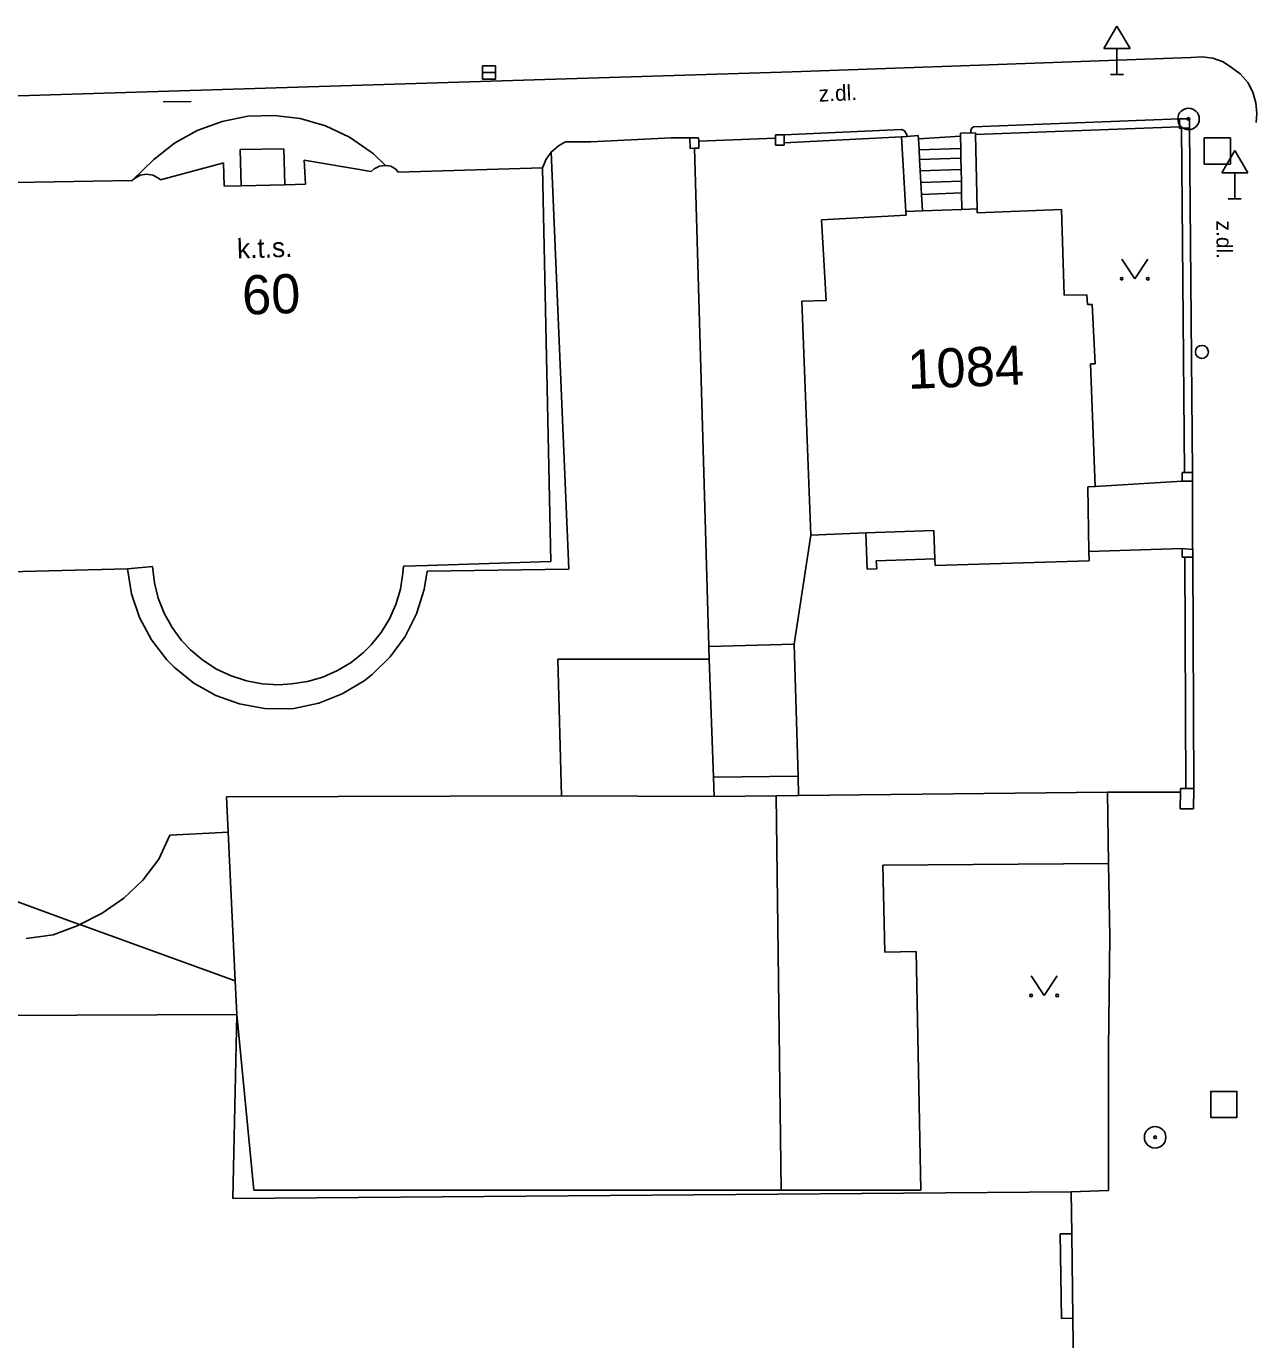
# Model space of a CAD drawing. Extents: x -642282 to -641982, y -1041678 to -1041427.
# Drawn here: x -642054.4 to -642007.5, y -1041554.9 to -1041504.6 of the extents above; entities that cross this region are included whole.
import ezdxf

# ---------------------------------------------------------------- set-up
doc = ezdxf.new("R2010")
doc.units = 0
for name, color, linetype in [('Budovy', 7, 'Continuous'), ('Ploty', 7, 'Continuous'), ('Pol_bod_pole', 7, 'Continuous'), ('Popis objektů', 7, 'Continuous'), ('Popis povrchů', 7, 'Continuous'), ('Popis ČP_ ČE', 7, 'Continuous'), ('Pris-HUP', 7, 'Continuous'), ('Rozhraní ploch 1', 7, 'Continuous'), ('Rozhraní ploch 2', 7, 'Continuous'), ('Svodidla_zábr_', 7, 'Continuous'), ('Vstup na pozemky', 7, 'Continuous'), ('Znaky kanalizace', 7, 'Continuous'), ('Znaky plyn', 7, 'Continuous'), ('Značky doprava', 7, 'Continuous'), ('Značky KM', 7, 'Continuous'), ('Šachty ner_', 7, 'Continuous')]:
    doc.layers.add(name, color=color, linetype=linetype)

msp = doc.modelspace()

# ---------------------------------------------------------------- linework, layer by layer
at = {"layer": 'Budovy'}
for p, q in [((-642046.925, -1041508.274), (-642045.936, -1041508.08)), ((-642045.936, -1041508.08), (-642044.929, -1041508.044)), ((-642044.929, -1041508.044), (-642043.929, -1041508.169)), ((-642048.75, -1041509.114), (-642047.871, -1041508.621)), ((-642047.871, -1041508.621), (-642046.925, -1041508.274)), ((-642043.929, -1041508.169), (-642042.961, -1041508.449)), ((-642042.961, -1041508.449), (-642042.049, -1041508.879)), ((-642049.54, -1041509.74), (-642048.75, -1041509.114)), ((-642042.049, -1041508.879), (-642041.217, -1041509.448)), ((-642041.217, -1041509.448), (-642041.13, -1041509.52)), ((-642041.13, -1041509.52), (-642040.667, -1041509.959)), ((-642050.36, -1041510.54), (-642049.54, -1041509.74)), ((-642049.28, -1041510.51), (-642046.91, -1041509.87)), ((-642046.91, -1041509.87), (-642046.87, -1041509.86)), ((-642046.841, -1041510.76), (-642046.87, -1041509.86)), ((-642043.73, -1041510.68), (-642043.78, -1041509.76)), ((-642043.78, -1041509.76), (-642041.22, -1041510.19)), ((-642041.106, -1041510.086), (-642041.22, -1041510.19)), ((-642040.898, -1041509.984), (-642041.106, -1041510.086)), ((-642040.667, -1041509.959), (-642040.898, -1041509.984)), ((-642040.667, -1041509.959), (-642040.456, -1041509.995)), ((-642040.456, -1041509.995), (-642040.272, -1041510.106)), ((-642040.272, -1041510.106), (-642040.179, -1041510.213)), ((-642040.179, -1041510.213), (-642034.65, -1041510.05)), ((-642034.65, -1041510.05), (-642034.34, -1041525.13)), ((-642054.84, -1041510.62), (-642050.36, -1041510.54)), ((-642050.275, -1041510.458), (-642050.36, -1041510.54)), ((-642050.275, -1041510.458), (-642050.06, -1041510.34)), ((-642050.06, -1041510.34), (-642049.819, -1041510.296)), ((-642049.819, -1041510.296), (-642049.576, -1041510.333)), ((-642049.576, -1041510.333), (-642049.358, -1041510.444)), ((-642049.358, -1041510.444), (-642049.28, -1041510.51)), ((-642046.841, -1041510.76), (-642046.194, -1041510.743)), ((-642046.194, -1041510.743), (-642044.525, -1041510.7)), ((-642044.525, -1041510.7), (-642043.73, -1041510.68)), ((-642018.599, -1041511.644), (-642020.109, -1041511.704)), ((-642018.01, -1041511.62), (-642018.599, -1041511.644)), ((-642018.01, -1041511.78), (-642018.01, -1041511.62)), ((-642014.79, -1041511.65), (-642018.01, -1041511.78)), ((-642014.68, -1041514.93), (-642014.79, -1041511.65)), ((-642020.73, -1041511.87), (-642023.97, -1041512.04)), ((-642023.97, -1041512.04), (-642023.8, -1041515.14)), ((-642020.109, -1041511.704), (-642020.75, -1041511.73)), ((-642020.73, -1041511.87), (-642020.75, -1041511.73)), ((-642023.8, -1041515.14), (-642024.72, -1041515.16)), ((-642024.72, -1041515.16), (-642024.38, -1041524.12)), ((-642014.68, -1041514.93), (-642013.81, -1041514.92)), ((-642013.791, -1041515.29), (-642013.81, -1041514.92)), ((-642013.61, -1041515.29), (-642013.791, -1041515.29)), ((-642013.61, -1041515.29), (-642013.5, -1041517.56)), ((-642013.674, -1041517.567), (-642013.5, -1041517.56)), ((-642013.49, -1041522.26), (-642013.674, -1041517.567)), ((-642013.773, -1041522.271), (-642013.49, -1041522.26)), ((-642013.773, -1041522.271), (-642013.74, -1041524.75)), ((-642024.38, -1041524.12), (-642022.28, -1041524.04)), ((-642022.28, -1041524.04), (-642019.67, -1041523.94)), ((-642019.67, -1041523.94), (-642019.63, -1041525.03)), ((-642039.064, -1041525.282), (-642034.34, -1041525.13)), ((-642019.63, -1041525.03), (-642019.62, -1041525.29)), ((-642019.62, -1041525.29), (-642013.73, -1041525.11)), ((-642013.74, -1041524.75), (-642013.73, -1041525.11)), ((-642057.89, -1041525.6), (-642050.54, -1041525.42)), ((-642050.54, -1041525.42), (-642049.59, -1041525.33)), ((-642049.59, -1041525.33), (-642049.517, -1041525.944)), ((-642040.095, -1041526.187), (-642039.999, -1041525.583)), ((-642039.999, -1041525.583), (-642039.982, -1041525.312)), ((-642039.982, -1041525.312), (-642039.064, -1041525.282)), ((-642049.517, -1041525.944), (-642049.366, -1041526.543)), ((-642040.268, -1041526.774), (-642040.095, -1041526.187)), ((-642049.366, -1041526.543), (-642049.139, -1041527.117)), ((-642049.139, -1041527.117), (-642048.839, -1041527.658)), ((-642040.516, -1041527.333), (-642040.268, -1041526.774)), ((-642048.839, -1041527.658), (-642048.472, -1041528.155)), ((-642040.836, -1041527.854), (-642040.516, -1041527.333)), ((-642048.472, -1041528.155), (-642048.13, -1041528.52)), ((-642041.22, -1041528.33), (-642040.836, -1041527.854)), ((-642048.13, -1041528.52), (-642047.658, -1041528.918)), ((-642041.984, -1041528.996), (-642041.506, -1041528.615)), ((-642041.506, -1041528.615), (-642041.22, -1041528.33)), ((-642028.29, -1041528.39), (-642025.02, -1041528.3)), ((-642028.27, -1041528.88), (-642028.29, -1041528.39)), ((-642024.87, -1041533.35), (-642025.02, -1041528.3)), ((-642047.658, -1041528.918), (-642047.138, -1041529.253)), ((-642047.138, -1041529.253), (-642046.58, -1041529.517)), ((-642042.508, -1041529.313), (-642041.984, -1041528.996)), ((-642033.93, -1041534.11), (-642034.07, -1041528.88)), ((-642034.07, -1041528.88), (-642028.27, -1041528.88)), ((-642028.11, -1041533.39), (-642028.27, -1041528.88)), ((-642046.58, -1041529.517), (-642045.992, -1041529.707)), ((-642045.992, -1041529.707), (-642045.384, -1041529.819)), ((-642044.26, -1041529.82), (-642043.655, -1041529.728)), ((-642043.655, -1041529.728), (-642043.068, -1041529.558)), ((-642043.068, -1041529.558), (-642042.508, -1041529.313)), ((-642045.384, -1041529.819), (-642044.767, -1041529.853)), ((-642044.767, -1041529.853), (-642044.26, -1041529.82)), ((-642028.11, -1041533.39), (-642024.87, -1041533.35)), ((-642028.08, -1041534.14), (-642028.11, -1041533.39)), ((-642033.93, -1041534.11), (-642028.08, -1041534.14)), ((-642046.36, -1041542.48), (-642063.49, -1041542.57)), ((-642046.51, -1041549.53), (-642046.36, -1041542.48)), ((-642046.51, -1041549.53), (-642014.41, -1041549.28)), ((-642014.39, -1041550.89), (-642014.41, -1041549.28)), ((-642014.83, -1041550.89), (-642014.39, -1041550.89)), ((-642014.79, -1041554.125), (-642014.83, -1041550.89)), ((-642014.35, -1041554.12), (-642014.39, -1041550.89)), ((-642014.35, -1041554.12), (-642014.79, -1041554.125)), ((-642014.32, -1041556.74), (-642014.35, -1041554.12))]:
    msp.add_line(p, q, dxfattribs=at)
at = {"layer": 'Ploty'}
for p, q in [((-642025.4, -1041508.79), (-642020.91, -1041508.58)), ((-642018.26, -1041508.71), (-642018.25, -1041508.63)), ((-642018.16, -1041508.48), (-642010.27, -1041508.18)), ((-642018.08, -1041508.78), (-642010.27, -1041508.48)), ((-642010.19, -1041508.538), (-642010.07, -1041521.73)), ((-642009.89, -1041508.53), (-642009.77, -1041521.73)), ((-642032.8, -1041509.06), (-642033.77, -1041509.06)), ((-642029.01, -1041508.91), (-642029.73, -1041508.91)), ((-642025.4, -1041509.091), (-642020.91, -1041508.86)), ((-642028.29, -1041528.39), (-642028.833, -1041509.305)), ((-642010.06, -1041524.97), (-642010.02, -1041533.83)), ((-642009.76, -1041524.97), (-642009.72, -1041533.83)), ((-642010.232, -1041533.97), (-642013.023, -1041533.974)), ((-642012.98, -1041543.82), (-642012.99, -1041549.23)), ((-642014.41, -1041549.28), (-642012.99, -1041549.23))]:
    msp.add_line(p, q, dxfattribs=at)
for points in [[(-642020.91, -1041508.58), (-642020.81, -1041508.62), (-642020.71, -1041508.78), (-642020.709, -1041508.847)], [(-642018.16, -1041508.48), (-642018.23, -1041508.55), (-642018.25, -1041508.63)], [(-642034.65, -1041510.05), (-642034.514, -1041509.726), (-642034.33, -1041509.45), (-642034.045, -1041509.211), (-642033.77, -1041509.06)], [(-642013.023, -1041533.974), (-642012.982, -1041536.704), (-642012.94, -1041539.51)]]:
    msp.add_lwpolyline(points, dxfattribs=at)
at = {"layer": 'Pol_bod_pole'}
for centre, radius in [((-642009.92, -1041508.18), 0.412), ((-642009.92, -1041508.18), 0.05), ((-642011.2, -1041547.19), 0.412), ((-642011.2, -1041547.19), 0.05)]:
    msp.add_circle(centre, radius, dxfattribs=at)
at = {"layer": 'Pris-HUP'}
for p, q in [((-642009.73, -1041534.61), (-642009.72, -1041533.83)), ((-642010.24, -1041534.61), (-642009.73, -1041534.61))]:
    msp.add_line(p, q, dxfattribs=at)
for points in [[(-642010.24, -1041534.61), (-642010.232, -1041533.97), (-642010.23, -1041533.83)], [(-642010.23, -1041533.83), (-642010.02, -1041533.83), (-642009.72, -1041533.83)]]:
    msp.add_lwpolyline(points, dxfattribs=at)
at = {"layer": 'Rozhraní ploch 1'}
for p, q in [((-642025.1, -1041506.37), (-642017.93, -1041506.12)), ((-642017.93, -1041506.12), (-642009.82, -1041505.83)), ((-642087.54, -1041508.33), (-642025.1, -1041506.37)), ((-642020.239, -1041509.369), (-642018.64, -1041509.311)), ((-642020.218, -1041509.738), (-642018.634, -1041509.681)), ((-642020.194, -1041510.168), (-642018.626, -1041510.111)), ((-642020.169, -1041510.618), (-642018.618, -1041510.561)), ((-642020.144, -1041511.068), (-642018.61, -1041511.012)), ((-642013.49, -1041522.26), (-642010.17, -1041522.05)), ((-642013.74, -1041524.75), (-642010.16, -1041524.64))]:
    msp.add_line(p, q, dxfattribs=at)
msp.add_lwpolyline([(-642009.82, -1041505.83), (-642009.404, -1041505.804), (-642008.991, -1041505.858), (-642008.596, -1041505.99), (-642008.28, -1041506.21), (-642007.95, -1041506.45), (-642007.656, -1041506.79), (-642007.463, -1041507.159), (-642007.344, -1041507.559), (-642007.303, -1041507.973), (-642007.33, -1041508.32)], dxfattribs=at)
at = {"layer": 'Rozhraní ploch 2'}
for p, q in [((-642009.89, -1041508.17), (-642010.27, -1041508.18)), ((-642009.89, -1041508.53), (-642009.89, -1041508.17)), ((-642028.68, -1041508.9), (-642029.01, -1041508.91)), ((-642029.01, -1041508.91), (-642028.998, -1041509.31)), ((-642025.4, -1041508.79), (-642025.74, -1041508.79)), ((-642020.75, -1041511.73), (-642020.91, -1041508.86)), ((-642044.56, -1041509.32), (-642046.23, -1041509.35)), ((-642046.194, -1041510.743), (-642046.23, -1041509.35)), ((-642044.525, -1041510.7), (-642044.56, -1041509.32)), ((-642033.65, -1041525.43), (-642034.33, -1041509.45)), ((-642025.4, -1041509.19), (-642025.74, -1041509.19)), ((-642010.17, -1041522.05), (-642010.17, -1041521.73)), ((-642009.77, -1041522.05), (-642010.17, -1041522.05)), ((-642009.77, -1041522.05), (-642009.77, -1041521.73)), ((-642024.38, -1041524.12), (-642025.02, -1041528.3)), ((-642022.28, -1041524.04), (-642022.23, -1041525.43)), ((-642010.16, -1041524.97), (-642010.16, -1041524.64)), ((-642009.76, -1041524.97), (-642009.76, -1041524.64)), ((-642021.88, -1041525.11), (-642019.63, -1041525.03)), ((-642021.86, -1041525.42), (-642021.88, -1041525.11)), ((-642039.07, -1041525.5), (-642033.65, -1041525.43)), ((-642022.23, -1041525.43), (-642021.86, -1041525.42)), ((-642024.85, -1041534.1), (-642024.87, -1041533.35)), ((-642033.93, -1041534.11), (-642046.75, -1041534.15)), ((-642046.75, -1041534.15), (-642046.69, -1041535.5)), ((-642028.08, -1041534.14), (-642025.71, -1041534.11)), ((-642025.71, -1041534.11), (-642024.85, -1041534.1)), ((-642025.71, -1041534.11), (-642025.52, -1041549.22)), ((-642024.85, -1041534.1), (-642013.023, -1041533.974)), ((-642049.35, -1041536.54), (-642048.92, -1041535.61)), ((-642048.92, -1041535.61), (-642046.92, -1041535.51)), ((-642046.92, -1041535.51), (-642046.69, -1041535.5)), ((-642046.69, -1041535.5), (-642046.42, -1041541.2)), ((-642049.96, -1041537.34), (-642049.35, -1041536.54)), ((-642021.62, -1041536.77), (-642012.982, -1041536.704)), ((-642021.55, -1041540.1), (-642021.62, -1041536.77)), ((-642056.14, -1041537.66), (-642052.42, -1041539.02)), ((-642050.69, -1041538.03), (-642049.96, -1041537.34)), ((-642051.51, -1041538.61), (-642050.69, -1041538.03)), ((-642052.37, -1041539.04), (-642051.51, -1041538.61)), ((-642053.39, -1041539.43), (-642052.47, -1041539.09)), ((-642052.47, -1041539.09), (-642052.37, -1041539.04)), ((-642052.42, -1041539.02), (-642052.37, -1041539.04)), ((-642052.37, -1041539.04), (-642046.42, -1041541.2)), ((-642054.43, -1041539.58), (-642053.39, -1041539.43)), ((-642020.35, -1041540.07), (-642021.55, -1041540.1)), ((-642020.17, -1041549.22), (-642020.35, -1041540.07)), ((-642046.36, -1041542.48), (-642046.42, -1041541.2)), ((-642046.36, -1041542.48), (-642045.71, -1041549.21)), ((-642045.71, -1041549.21), (-642025.52, -1041549.22)), ((-642025.52, -1041549.22), (-642020.17, -1041549.22))]:
    msp.add_line(p, q, dxfattribs=at)
for points in [[(-642010.27, -1041508.18), (-642010.27, -1041508.48), (-642010.27, -1041508.54)], [(-642009.89, -1041508.53), (-642010.19, -1041508.538), (-642010.27, -1041508.54)], [(-642028.68, -1041508.9), (-642028.676, -1041509.026), (-642028.668, -1041509.3)], [(-642025.74, -1041509.19), (-642025.74, -1041508.916), (-642025.74, -1041508.79)], [(-642025.4, -1041508.79), (-642025.4, -1041509.091), (-642025.4, -1041509.19)], [(-642020.27, -1041508.82), (-642020.709, -1041508.847), (-642020.91, -1041508.86)], [(-642020.109, -1041511.704), (-642020.144, -1041511.068), (-642020.169, -1041510.618), (-642020.194, -1041510.168), (-642020.218, -1041509.738), (-642020.239, -1041509.369), (-642020.263, -1041508.938), (-642020.27, -1041508.82)], [(-642018.06, -1041508.73), (-642018.26, -1041508.71), (-642018.65, -1041508.72)], [(-642018.599, -1041511.644), (-642018.61, -1041511.012), (-642018.618, -1041510.561), (-642018.626, -1041510.111), (-642018.634, -1041509.681), (-642018.64, -1041509.311), (-642018.648, -1041508.839), (-642018.65, -1041508.72)], [(-642018.01, -1041511.62), (-642018.08, -1041508.78), (-642018.06, -1041508.73)], [(-642028.668, -1041509.3), (-642028.833, -1041509.305), (-642028.998, -1041509.31)], [(-642010.17, -1041521.73), (-642010.07, -1041521.73), (-642009.77, -1041521.73)], [(-642010.16, -1041524.64), (-642009.77, -1041524.67), (-642009.76, -1041524.64)], [(-642009.76, -1041524.97), (-642010.06, -1041524.97), (-642010.16, -1041524.97)], [(-642050.54, -1041525.42), (-642050.388, -1041526.371), (-642050.08, -1041527.284), (-642049.626, -1041528.133), (-642049.038, -1041528.896), (-642048.75, -1041529.19)], [(-642041.18, -1041529.46), (-642040.486, -1041528.783), (-642039.912, -1041528.001), (-642039.474, -1041527.135), (-642039.184, -1041526.209), (-642039.07, -1041525.5)], [(-642048.75, -1041529.19), (-642047.999, -1041529.793), (-642047.159, -1041530.265), (-642046.253, -1041530.59), (-642045.305, -1041530.762), (-642044.342, -1041530.775), (-642044.17, -1041530.76)], [(-642044.17, -1041530.76), (-642043.222, -1041530.556), (-642042.32, -1041530.199), (-642041.489, -1041529.698), (-642041.18, -1041529.46)]]:
    msp.add_lwpolyline(points, dxfattribs=at)
at = {"layer": 'Svodidla_zábr_'}
msp.add_line((-642049.18, -1041507.53), (-642048.11, -1041507.51), dxfattribs=at)
at = {"layer": 'Vstup na pozemky'}
for p, q in [((-642029.73, -1041508.91), (-642032.8, -1041509.06)), ((-642028.676, -1041509.026), (-642025.74, -1041508.916)), ((-642020.263, -1041508.938), (-642018.648, -1041508.839)), ((-642009.77, -1041522.05), (-642009.77, -1041524.67)), ((-642012.94, -1041539.51), (-642012.98, -1041543.82))]:
    msp.add_line(p, q, dxfattribs=at)
at = {"layer": 'Znaky kanalizace'}
msp.add_line((-642036.95, -1041506.4), (-642036.45, -1041506.4), dxfattribs=at)
msp.add_lwpolyline([(-642036.95, -1041506.65), (-642036.45, -1041506.65), (-642036.45, -1041506.15), (-642036.95, -1041506.15)], close=True, dxfattribs=at)
at = {"layer": 'Znaky plyn'}
msp.add_circle((-642009.408, -1041517.104), 0.25, dxfattribs=at)
at = {"layer": 'Značky doprava'}
for p, q in [((-642013.16, -1041505.48), (-642012.66, -1041504.63)), ((-642012.66, -1041504.63), (-642012.16, -1041505.48)), ((-642013.16, -1041505.48), (-642012.16, -1041505.48)), ((-642012.66, -1041506.48), (-642012.66, -1041505.48)), ((-642012.91, -1041506.48), (-642012.41, -1041506.48)), ((-642008.65, -1041510.24), (-642008.15, -1041509.39)), ((-642008.15, -1041509.39), (-642007.65, -1041510.24)), ((-642008.65, -1041510.24), (-642007.65, -1041510.24)), ((-642008.15, -1041511.24), (-642008.15, -1041510.24)), ((-642008.4, -1041511.24), (-642007.9, -1041511.24))]:
    msp.add_line(p, q, dxfattribs=at)
at = {"layer": 'Značky KM'}
for p, q in [((-642012.48, -1041513.55), (-642011.98, -1041514.3)), ((-642011.98, -1041514.3), (-642011.48, -1041513.55)), ((-642015.95, -1041541.01), (-642015.45, -1041541.76)), ((-642015.45, -1041541.76), (-642014.95, -1041541.01))]:
    msp.add_line(p, q, dxfattribs=at)
for centre in [(-642012.48, -1041514.3), (-642011.48, -1041514.3), (-642015.95, -1041541.76), (-642014.95, -1041541.76)]:
    msp.add_circle(centre, 0.05, dxfattribs=at)
at = {"layer": 'Šachty ner_'}
for points in [[(-642009.32, -1041509.91), (-642008.32, -1041509.91), (-642008.32, -1041508.91), (-642009.32, -1041508.91)], [(-642009.07, -1041546.43), (-642008.07, -1041546.43), (-642008.07, -1041545.43), (-642009.07, -1041545.43)]]:
    msp.add_lwpolyline(points, close=True, dxfattribs=at)

# ---------------------------------------------------------------- texts
at = {"layer": 'Popis objektů'}
msp.add_text('k.t.s.', height=0.75, rotation=1.8536, dxfattribs=at).set_placement((-642046.34, -1041513.528))
at = {"layer": 'Popis povrchů'}
for rotation, p in [(2.6778, (-642024.068, -1041507.522)), (270.1282, (-642008.851, -1041512.075))]:
    msp.add_text('z.dl.', height=0.6, rotation=rotation, dxfattribs=at).set_placement(p)
at = {"layer": 'Popis ČP_ ČE'}
for s, rotation, p in [('60', 1.8536, (-642046.135, -1041515.68)), ('1084', 2.2513, (-642020.658, -1041518.525))]:
    msp.add_text(s, height=1.5, rotation=rotation, dxfattribs=at).set_placement(p)

doc.saveas('drawing.dxf')
